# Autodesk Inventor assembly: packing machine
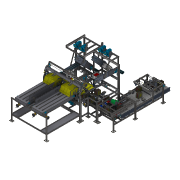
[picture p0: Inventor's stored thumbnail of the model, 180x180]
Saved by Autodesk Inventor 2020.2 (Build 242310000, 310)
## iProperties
Created: 2019-10
Part Number: packing machine
Document SubType Name: Assembly
Designer: lutzd
Mass: 9.16188e+07 g
Surface Area: 2.08283e+06 cm^2
Volume: 1.17693e+07 cm^3
Density: 7.78456 g/cm^3
VLDS_Profile: Default Assembly
VLDS_TimeStamp: 2016-07-29
VLDS_FailCnt: 0
VLDS_AcceptCnt: 0
Dimensions: 6258,9x3054,9x3920,3 mm
Mass: 91618,784 kg
DocNumber: ADSK-014309
Folder: 01 - Themengebiete\Simplification\01 - Packaging machine\
VDS_Category: 3D Komponenten
VDS_NumSchm: Autodesk
Title: packaging machine
Author: lutzd
Revision Number: -
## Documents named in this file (6)
- D:\07 - DEMODATEN\OTX 2019 - Dataset - UPDATE - Dez2019\Designs\07-Packing machine\_packing machine.iam
- D:\07 - DEMODATEN\OTX 2019 - Dataset - UPDATE - Dez2019\Designs\07-Packing machine\ADSK-014168.iam
- D:\07 - DEMODATEN\OTX 2019 - Dataset - UPDATE - Dez2019\Designs\07-Packing machine\ADSK-014308.iam
- D:\07 - DEMODATEN\OTX 2019 - Dataset - UPDATE - Dez2019\Designs\07-Packing machine\MOD-029310.iam
- D:\07 - DEMODATEN\OTX 2019 - Dataset - UPDATE - Dez2019\Designs\07-Packing machine\Parts\ADSK-014502.ipt
- MOD-029310.iam
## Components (4 placed, 4 different names)
1. ADSK-014168:1 [sub-assembly] — Passend:2, Fluchtend:1, Passend:4, Fluchtend:2, Passend:5, Passend:6, Passend:8
2. ADSK-014308:1 [sub-assembly] — Passend:1, Passend:2, Fluchtend:1
3. MOD-029310:1 [sub-assembly] — Passend:3, Passend:4, Fluchtend:2, Passend:5, Passend:6, Passend:7, Passend:9
4. ADSK-014502:1 — Passend:7, Passend:8, Passend:9
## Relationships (11: Mate 9, Flush 2)
- Passend:1 [Mate]: ADSK-014308:1
- Passend:2 [Mate]: ADSK-014168:1 ↔ ADSK-014308:1
- Fluchtend:1 [Flush]: ADSK-014168:1 ↔ ADSK-014308:1
- Passend:3 [Mate]: MOD-029310:1
- Passend:4 [Mate]: ADSK-014168:1 ↔ MOD-029310:1
- Fluchtend:2 [Flush]: ADSK-014168:1 ↔ MOD-029310:1
- Passend:5 [Mate]: ADSK-014168:1 ↔ MOD-029310:1
- Passend:6 [Mate]: ADSK-014168:1 ↔ MOD-029310:1
- Passend:7 [Mate]: MOD-029310:1 ↔ ADSK-014502:1
- Passend:8 [Mate]: ADSK-014168:1 ↔ ADSK-014502:1
- Passend:9 [Mate]: MOD-029310:1 ↔ ADSK-014502:1
